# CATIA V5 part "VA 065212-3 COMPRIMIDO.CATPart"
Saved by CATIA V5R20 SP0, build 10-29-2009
Part number: VA 065212-3 COMPRIMIDO
Revision: ANY
Definition: UNKNOWN
Nomenclature: VA 065212-3 COMPRIMIDO
Source: Unknown
Bounding box of the stored display mesh (mm): x -1.9 to 1.9, y 0 to 4.25, z -1.9 to 1.9
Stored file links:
  C:\Users\Utente\Desktop\IO LAVORO\3D X SITO CF\CUMSA\3D files VA\VA 065212\VA 065212-3 COMPRIMIDO.CATPart
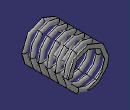
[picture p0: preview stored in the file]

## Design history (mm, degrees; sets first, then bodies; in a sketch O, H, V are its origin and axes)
Body1 "Cortar-Extruir1" (main body)
  Solid1: solid without history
